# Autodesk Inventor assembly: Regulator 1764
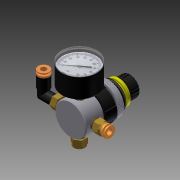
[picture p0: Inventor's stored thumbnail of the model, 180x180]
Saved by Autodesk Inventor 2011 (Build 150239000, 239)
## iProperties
Created: 2010-02
Part Number: Regulator 1764
Document SubType Name: Assembly
Designer: jgehrig
Author: jgehrig
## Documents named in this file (9)
- R:\CAD Archives\Pneumatics\Regulator 1764\Regulator 1764.iam
- R:\CAD Archives\Pneumatics\Regulator 1764\Regulator Base 1764.ipt
- R:\CAD Archives\Pneumatics\Regulator 1764\Regulator Middle 1764.ipt
- R:\CAD Archives\Pneumatics\Regulator 1764\PSI Gage 1764\PSI Gauge 1764.iam
- R:\CAD Archives\Pneumatics\Regulator 1764\Regulator Ring 1 1764.ipt
- R:\CAD Archives\Pneumatics\Regulator 1764\Regulator Ring 2 1764.ipt
- R:\CAD Archives\Pneumatics\Regulator 1764\Pneumatic Screw 1764\Pneumatic Screw 1764.iam
- R:\CAD Archives\Pneumatics\Regulator 1764\Pneumatics Bend Piece 1764\Pneumatic Bend Piece 1764.iam
- R:\CAD Archives\Pneumatics\Regulator 1764\Pneumatic Screw 1764\Pneumatic Screw Part 1 1764.ipt
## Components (8 placed, 8 different names)
1. Regulator Base 1764:1 — Insert:1, Mate:1, Tangent:1, Mate:2, Tangent:2, Mate:3, Tangent:3, Mate:4, Tangent:4
2. Regulator Middle 1764:1 — Insert:1, Insert:2, Insert:3, Angle:1
3. Regulator Ring 1 1764:1 — Insert:3
4. Regulator Ring 2 1764:1 — Insert:2
5. PSI Gauge 1764:1 [sub-assembly] — Mate:1, Tangent:1, Angle:1, Angle:2
6. Pneumatic Screw 1764:1 [sub-assembly] — Mate:2, Tangent:2
7. Pneumatic Bend Piece 1764:1 [sub-assembly] — Mate:3, Tangent:3, Angle:2
8. Pneumatic Screw Part 1 1764:1 — Mate:4, Tangent:4
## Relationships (13: Mate 4, Tangent 4, Insert 3, Angle 2)
- Insert:1: Regulator Base 1764:1 ↔ Regulator Middle 1764:1
- Insert:2: Regulator Middle 1764:1 ↔ Regulator Ring 2 1764:1
- Insert:3: Regulator Middle 1764:1 ↔ Regulator Ring 1 1764:1
- Mate:1: Regulator Base 1764:1 ↔ PSI Gauge 1764:1
- Tangent:1: Regulator Base 1764:1 ↔ PSI Gauge 1764:1
- Angle:1: Regulator Middle 1764:1 ↔ PSI Gauge 1764:1
- Mate:2: Regulator Base 1764:1 ↔ Pneumatic Screw 1764:1
- Tangent:2: Regulator Base 1764:1 ↔ Pneumatic Screw 1764:1
- Mate:3: Regulator Base 1764:1 ↔ Pneumatic Bend Piece 1764:1
- Tangent:3: Regulator Base 1764:1 ↔ Pneumatic Bend Piece 1764:1
- Angle:2: PSI Gauge 1764:1 ↔ Pneumatic Bend Piece 1764:1
- Mate:4: Regulator Base 1764:1 ↔ Pneumatic Screw Part 1 1764:1
- Tangent:4: Regulator Base 1764:1 ↔ Pneumatic Screw Part 1 1764:1
